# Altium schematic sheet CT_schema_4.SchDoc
size 302 x 170 mm
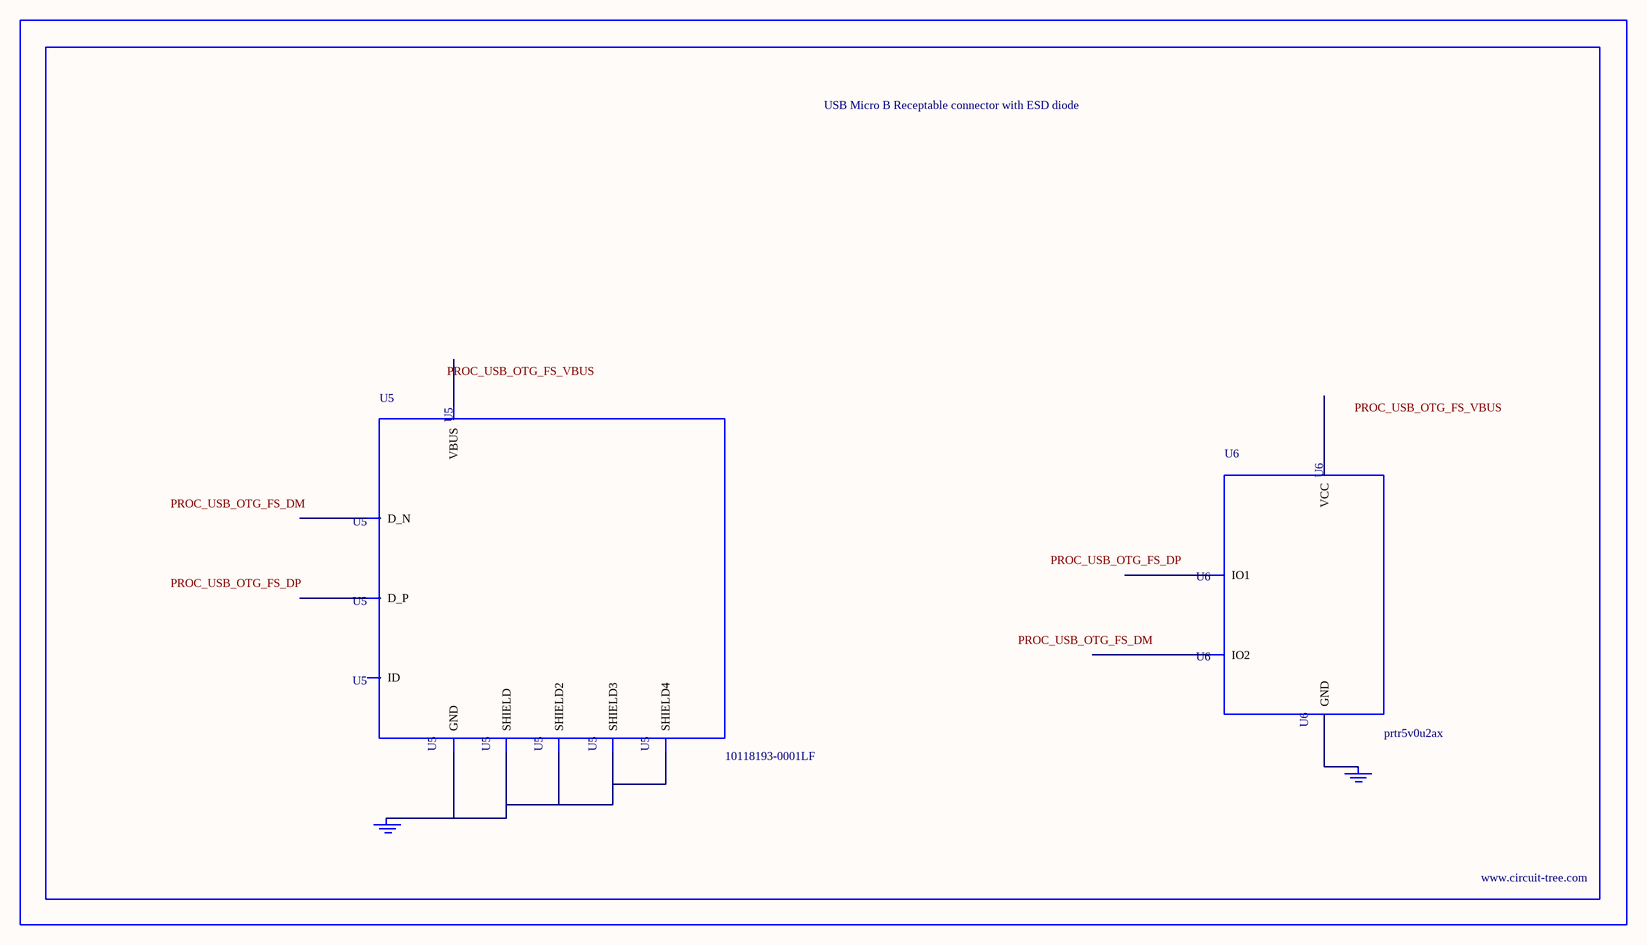
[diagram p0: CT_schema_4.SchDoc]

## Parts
BORDER3  (no value)
GND_INSTANCE_3_0  (no value)
GND_INSTANCE_3_1  (no value)
U5  10118193-0001LF  [FCI_10118193-0001LF]
U6  prtr5v0u2ax  [SOT143B]

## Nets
NetGND_INSTANCE_3_0_0: GND_INSTANCE_3_0.0(GND) U5.5(GND) U5.6(SHIELD) U5.7(SHIELD2) U5.8(SHIELD3) U5.9(SHIELD4)
NetGND_INSTANCE_3_1_0: GND_INSTANCE_3_1.0(GND) U6.1(GND)

Not connected (* = marked no-connect by the designer): U5 1(VBUS) 2(D_N) 3(D_P) 4(ID); U6 2(IO1) 3(IO2) 4(VCC)

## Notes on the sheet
- Labels drawn without touching a wire or pin: PROC_USB_OTG_FS_DM, PROC_USB_OTG_FS_DP, PROC_USB_OTG_FS_VBUS

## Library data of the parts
BORDER3 = BORDER_PAGE3
GND_INSTANCE_3_0 GND_INSTANCE_3_1 = GND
